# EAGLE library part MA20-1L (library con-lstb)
PIN HEADER
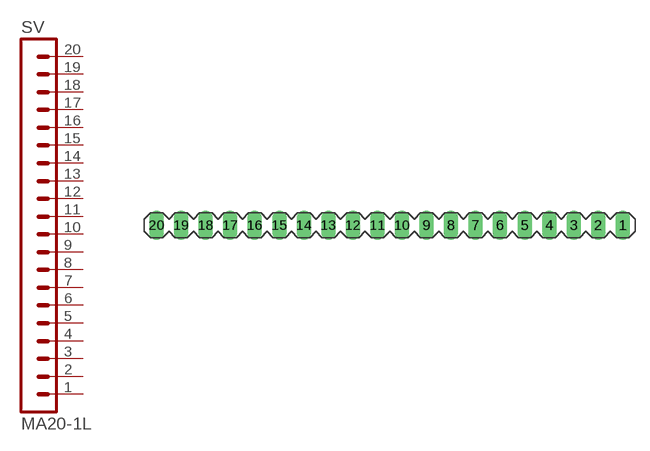
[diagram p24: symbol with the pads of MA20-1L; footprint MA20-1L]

Designator prefix SV

## MA20-1L (OC_FARNELL: unknown; OC_NEWARK: unknown)  [MA20-1L]
1  1  pas
2  2  pas
3  3  pas
4  4  pas
5  5  pas
6  6  pas
7  7  pas
8  8  pas
9  9  pas
10  10  pas
11  11  pas
12  12  pas
13  13  pas
14  14  pas
15  15  pas
16  16  pas
17  17  pas
18  18  pas
19  19  pas
20  20  pas

## Footprint MA20-1L (pad centres in mm)
PIN HEADER
drill 1.016 long: 1 24.13,0; 2 21.59,0; 3 19.05,0; 4 16.51,0; 5 13.97,0; 6 11.43,0; 7 8.89,0; 8 6.35,0; 9 3.81,0; 10 1.27,0; 11 -1.27,0; 12 -3.81,0; 13 -6.35,0; 14 -8.89,0; 15 -11.43,0; 16 -13.97,0; 17 -16.51,0; 18 -19.05,0; 19 -21.59,0; 20 -24.13,0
